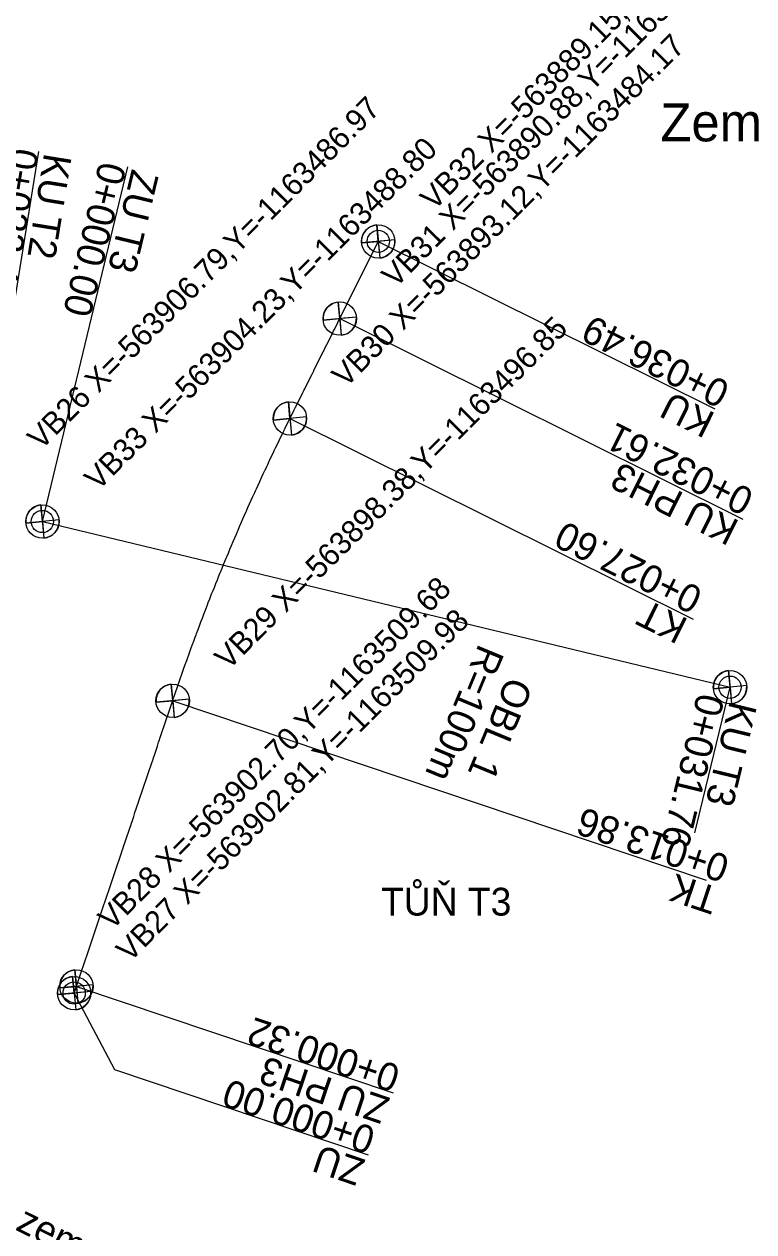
# Model space of a CAD drawing. Extents: x -564052 to -563798, y -1163587 to -1163361.
# Drawn here: x -563905 to -563872.3, y -1163520.7 to -1163466.5 of the extents above; entities that cross this region are included whole.
import ezdxf

# ---------------------------------------------------------------- set-up
doc = ezdxf.new("R2010")
doc.units = 0
for name, color, linetype in [('4', 7, 'Continuous'), ('5', 7, 'Continuous'), ('_popis staničení PH3', 7, 'Continuous'), ('_popis staničení T2', 7, 'Continuous'), ('_popis staničení T3', 7, 'Continuous'), ('_rám C35', 7, 'Continuous'), ('Default', 7, 'Continuous')]:
    doc.layers.add(name, color=color, linetype=linetype)

msp = doc.modelspace()

# ---------------------------------------------------------------- linework, layer by layer
msp.add_lwpolyline([(-563902.805, -1163509.983), (-563902.486, -1163509.036), (-563902.357, -1163508.652), (-563902.167, -1163508.088), (-563901.848, -1163507.14), (-563901.528, -1163506.193), (-563901.209, -1163505.245), (-563900.89, -1163504.297), (-563900.761, -1163503.913), (-563900.665, -1163503.629), (-563900.664, -1163503.625), (-563900.605, -1163503.45), (-563900.571, -1163503.349), (-563900.546, -1163503.275), (-563900.487, -1163503.099), (-563900.428, -1163502.924), (-563900.369, -1163502.749), (-563900.31, -1163502.573), (-563900.252, -1163502.402), (-563900.251, -1163502.398), (-563900.191, -1163502.223), (-563900.132, -1163502.047), (-563900.073, -1163501.872), (-563900.014, -1163501.697), (-563899.955, -1163501.521), (-563899.933, -1163501.454), (-563899.896, -1163501.346), (-563899.837, -1163501.171), (-563899.778, -1163500.995), (-563899.719, -1163500.82), (-563899.66, -1163500.645), (-563899.613, -1163500.506), (-563899.601, -1163500.469), (-563899.542, -1163500.294), (-563899.483, -1163500.119), (-563899.424, -1163499.943), (-563899.365, -1163499.768), (-563899.306, -1163499.593), (-563899.294, -1163499.559), (-563899.247, -1163499.417), (-563899.188, -1163499.242), (-563899.129, -1163499.067), (-563899.07, -1163498.891), (-563899.011, -1163498.716), (-563898.975, -1163498.611), (-563898.952, -1163498.541), (-563898.893, -1163498.366), (-563898.833, -1163498.19), (-563898.774, -1163498.015), (-563898.715, -1163497.84), (-563898.656, -1163497.664), (-563898.656, -1163497.663), (-563898.597, -1163497.489), (-563898.538, -1163497.314), (-563898.479, -1163497.138), (-563898.42, -1163496.963), (-563898.381, -1163496.847), (-563898.361, -1163496.788), (-563898.337, -1163496.716), (-563898.302, -1163496.612), (-563898.242, -1163496.437), (-563898.182, -1163496.262), (-563898.122, -1163496.087), (-563898.061, -1163495.913), (-563898.012, -1163495.77), (-563898, -1163495.738), (-563897.939, -1163495.563), (-563897.878, -1163495.389), (-563897.816, -1163495.215), (-563897.753, -1163495.04), (-563897.691, -1163494.866), (-563897.677, -1163494.828), (-563897.628, -1163494.692), (-563897.625, -1163494.685), (-563897.565, -1163494.518), (-563897.501, -1163494.345), (-563897.437, -1163494.171), (-563897.373, -1163493.997), (-563897.333, -1163493.889), (-563897.309, -1163493.824), (-563897.244, -1163493.651), (-563897.179, -1163493.478), (-563897.113, -1163493.305), (-563897.048, -1163493.132), (-563896.982, -1163492.959), (-563896.979, -1163492.953), (-563896.915, -1163492.786), (-563896.849, -1163492.614), (-563896.82, -1163492.541), (-563896.781, -1163492.441), (-563896.714, -1163492.269), (-563896.646, -1163492.097), (-563896.617, -1163492.021), (-563896.578, -1163491.925), (-563896.51, -1163491.753), (-563896.442, -1163491.581), (-563896.373, -1163491.409), (-563896.303, -1163491.238), (-563896.245, -1163491.093), (-563896.234, -1163491.066), (-563896.164, -1163490.895), (-563896.094, -1163490.724), (-563896.023, -1163490.553), (-563895.967, -1163490.416), (-563895.952, -1163490.382), (-563895.881, -1163490.211), (-563895.863, -1163490.169), (-563895.81, -1163490.04), (-563895.738, -1163489.87), (-563895.666, -1163489.7), (-563895.593, -1163489.529), (-563895.521, -1163489.359), (-563895.473, -1163489.248), (-563895.447, -1163489.189), (-563895.374, -1163489.019), (-563895.3, -1163488.85), (-563895.226, -1163488.68), (-563895.152, -1163488.511), (-563895.078, -1163488.342), (-563895.073, -1163488.331), (-563895.064, -1163488.311), (-563895.003, -1163488.172), (-563894.927, -1163488.003), (-563894.852, -1163487.835), (-563894.776, -1163487.666), (-563894.7, -1163487.497), (-563894.664, -1163487.419), (-563894.623, -1163487.329), (-563894.546, -1163487.16), (-563894.469, -1163486.992), (-563894.392, -1163486.824), (-563894.314, -1163486.656), (-563894.246, -1163486.51), (-563894.236, -1163486.489), (-563894.158, -1163486.321), (-563894.114, -1163486.228), (-563894.079, -1163486.154), (-563894, -1163485.986), (-563893.921, -1163485.819), (-563893.841, -1163485.652), (-563893.819, -1163485.606), (-563893.761, -1163485.485), (-563893.681, -1163485.319), (-563893.601, -1163485.152), (-563893.52, -1163484.986), (-563893.439, -1163484.819), (-563893.383, -1163484.706), (-563893.357, -1163484.653), (-563893.275, -1163484.487), (-563893.193, -1163484.322), (-563893.116, -1163484.167), (-563893.111, -1163484.156), (-563893.028, -1163483.99), (-563892.946, -1163483.825), (-563892.939, -1163483.81), (-563892.863, -1163483.659), (-563892.781, -1163483.494), (-563892.698, -1163483.328), (-563892.616, -1163483.162), (-563892.533, -1163482.997), (-563892.493, -1163482.915), (-563892.451, -1163482.831), (-563892.368, -1163482.666), (-563892.286, -1163482.5), (-563892.203, -1163482.335), (-563892.121, -1163482.169), (-563892.047, -1163482.02), (-563892.038, -1163482.003), (-563891.956, -1163481.838), (-563891.873, -1163481.672), (-563891.791, -1163481.507), (-563891.708, -1163481.341), (-563891.626, -1163481.175), (-563891.601, -1163481.125), (-563891.543, -1163481.01), (-563891.461, -1163480.844), (-563891.378, -1163480.679), (-563891.296, -1163480.513), (-563891.213, -1163480.347), (-563891.155, -1163480.23), (-563891.131, -1163480.182), (-563891.048, -1163480.016), (-563890.966, -1163479.851), (-563889.152, -1163476.21), (-563889.15, -1163476.207)])
at = {"layer": '5'}
msp.add_line((-563904.23, -1163488.796), (-563873.359, -1163496.24), dxfattribs=at)
at = {"layer": '_popis staničení PH3'}
for points in [[(-563889.152, -1163476.21), (-563874.048, -1163483.736)], [(-563890.882, -1163479.681), (-563872.786, -1163488.697)], [(-563893.116, -1163484.167), (-563875.019, -1163493.183)], [(-563898.381, -1163496.847), (-563874.436, -1163504.911)], [(-563902.805, -1163509.983), (-563900.986, -1163513.414), (-563889.599, -1163517.249)], [(-563902.704, -1163509.683), (-563888.488, -1163514.47)]]:
    msp.add_lwpolyline(points, dxfattribs=at)
for centre in [(-563889.152, -1163476.21), (-563902.805, -1163509.983)]:
    msp.add_circle(centre, 0.5, dxfattribs=at)
at = {"layer": '_popis staničení T2'}
msp.add_lwpolyline([(-563906.789, -1163486.973), (-563904.394, -1163472.165)], dxfattribs=at)
at = {"layer": '_popis staničení T3'}
for points in [[(-563904.23, -1163488.796), (-563900.388, -1163472.866)], [(-563874.936, -1163502.781), (-563873.359, -1163496.24)]]:
    msp.add_lwpolyline(points, dxfattribs=at)
for centre in [(-563904.23, -1163488.796), (-563873.359, -1163496.24)]:
    msp.add_circle(centre, 0.5, dxfattribs=at)
at = {"layer": '_rám C35'}
for p, q in [((-563889.152, -1163476.21), (-563889.222, -1163475.463)), ((-563889.152, -1163476.21), (-563889.222, -1163475.463)), ((-563889.222, -1163475.464), (-563889.083, -1163476.957)), ((-563888.405, -1163476.141), (-563889.899, -1163476.28)), ((-563889.899, -1163476.28), (-563889.152, -1163476.21)), ((-563889.899, -1163476.28), (-563889.152, -1163476.21)), ((-563888.405, -1163476.141), (-563889.152, -1163476.21)), ((-563889.152, -1163476.21), (-563889.083, -1163476.958)), ((-563890.882, -1163479.681), (-563890.951, -1163478.934)), ((-563890.881, -1163479.681), (-563890.951, -1163478.934)), ((-563890.951, -1163478.935), (-563890.812, -1163480.428)), ((-563891.629, -1163479.751), (-563890.882, -1163479.681)), ((-563891.629, -1163479.751), (-563890.881, -1163479.681)), ((-563890.135, -1163479.612), (-563891.628, -1163479.751)), ((-563890.134, -1163479.612), (-563890.882, -1163479.681)), ((-563890.882, -1163479.681), (-563890.812, -1163480.429)), ((-563893.116, -1163484.167), (-563893.186, -1163483.419)), ((-563893.116, -1163484.167), (-563893.186, -1163483.419)), ((-563893.186, -1163483.42), (-563893.047, -1163484.913)), ((-563892.37, -1163484.097), (-563893.863, -1163484.236)), ((-563892.369, -1163484.097), (-563893.116, -1163484.167)), ((-563893.863, -1163484.236), (-563893.116, -1163484.167)), ((-563893.863, -1163484.236), (-563893.116, -1163484.167)), ((-563893.116, -1163484.167), (-563893.047, -1163484.914)), ((-563904.299, -1163488.049), (-563904.16, -1163489.542)), ((-563904.23, -1163488.796), (-563904.299, -1163488.049)), ((-563904.23, -1163488.796), (-563904.299, -1163488.049)), ((-563904.977, -1163488.865), (-563904.23, -1163488.796)), ((-563904.977, -1163488.865), (-563904.23, -1163488.796)), ((-563903.483, -1163488.726), (-563904.976, -1163488.865)), ((-563903.483, -1163488.726), (-563904.23, -1163488.796)), ((-563904.23, -1163488.796), (-563904.16, -1163489.543)), ((-563873.358, -1163496.24), (-563873.428, -1163495.492)), ((-563873.428, -1163495.493), (-563873.289, -1163496.986)), ((-563873.359, -1163496.24), (-563873.428, -1163495.493)), ((-563898.451, -1163496.1), (-563898.312, -1163497.594)), ((-563898.381, -1163496.847), (-563898.451, -1163496.1)), ((-563898.381, -1163496.847), (-563898.451, -1163496.1)), ((-563874.106, -1163496.309), (-563873.359, -1163496.24)), ((-563874.106, -1163496.309), (-563873.358, -1163496.24)), ((-563872.612, -1163496.17), (-563874.105, -1163496.309)), ((-563872.611, -1163496.17), (-563873.359, -1163496.24)), ((-563873.359, -1163496.24), (-563873.289, -1163496.987)), ((-563897.634, -1163496.778), (-563899.128, -1163496.917)), ((-563899.128, -1163496.917), (-563898.381, -1163496.847)), ((-563899.128, -1163496.917), (-563898.381, -1163496.847)), ((-563897.634, -1163496.778), (-563898.381, -1163496.847)), ((-563898.381, -1163496.847), (-563898.312, -1163497.594)), ((-563902.704, -1163509.683), (-563902.773, -1163508.935)), ((-563902.773, -1163508.936), (-563902.634, -1163510.429)), ((-563902.704, -1163509.683), (-563902.773, -1163508.936)), ((-563901.957, -1163509.613), (-563903.45, -1163509.752)), ((-563902.805, -1163509.983), (-563902.875, -1163509.236)), ((-563902.805, -1163509.983), (-563902.875, -1163509.236)), ((-563902.875, -1163509.237), (-563902.736, -1163510.73)), ((-563901.957, -1163509.613), (-563902.704, -1163509.683)), ((-563902.058, -1163509.914), (-563903.552, -1163510.053)), ((-563903.552, -1163510.053), (-563902.805, -1163509.983)), ((-563903.552, -1163510.053), (-563902.805, -1163509.983)), ((-563903.451, -1163509.752), (-563902.704, -1163509.683)), ((-563903.451, -1163509.752), (-563902.704, -1163509.683)), ((-563902.058, -1163509.914), (-563902.805, -1163509.983)), ((-563902.805, -1163509.983), (-563902.736, -1163510.731)), ((-563902.704, -1163509.683), (-563902.634, -1163510.43))]:
    msp.add_line(p, q, dxfattribs=at)
for centre in [(-563889.152, -1163476.21), (-563890.882, -1163479.681), (-563893.116, -1163484.167), (-563904.23, -1163488.796), (-563873.359, -1163496.24), (-563898.381, -1163496.847), (-563902.704, -1163509.683), (-563902.805, -1163509.983)]:
    msp.add_circle(centre, 0.75, dxfattribs=at)
for centre, start, end in [((-563889.152, -1163476.21), 95.3168, 185.3168), ((-563889.152, -1163476.21), 95.3168, 185.3168), ((-563889.152, -1163476.21), 275.3168, 5.3168), ((-563890.882, -1163479.681), 95.3168, 185.3168), ((-563890.881, -1163479.681), 95.3168, 185.3168), ((-563890.882, -1163479.681), 275.3168, 5.3168), ((-563893.116, -1163484.167), 95.3168, 185.3168), ((-563893.116, -1163484.167), 95.3168, 185.3168), ((-563893.116, -1163484.167), 275.3168, 5.3168), ((-563904.23, -1163488.796), 95.3168, 185.3168), ((-563904.23, -1163488.796), 95.3168, 185.3168), ((-563904.23, -1163488.796), 275.3168, 5.3168), ((-563873.358, -1163496.24), 95.3168, 185.3168), ((-563873.359, -1163496.24), 95.3168, 185.3168), ((-563898.381, -1163496.847), 95.3168, 185.3168), ((-563898.381, -1163496.847), 95.3168, 185.3168), ((-563873.359, -1163496.24), 275.3168, 5.3168), ((-563898.381, -1163496.847), 275.3168, 5.3168), ((-563902.704, -1163509.683), 95.3168, 185.3168), ((-563902.704, -1163509.683), 95.3168, 185.3168), ((-563902.805, -1163509.983), 95.3168, 185.3168), ((-563902.805, -1163509.983), 95.3168, 185.3168), ((-563902.704, -1163509.683), 275.3168, 5.3168), ((-563902.805, -1163509.983), 275.3168, 5.3168)]:
    msp.add_arc(centre, 0.75, start, end, dxfattribs=at)

# ---------------------------------------------------------------- texts
at = {"layer": '4'}
for s, height, p in [('Zemní hrázka PH3', 1.70472, (-563876.485, -1163471.716)), ('TŮŇ T3', 1.25, (-563889.026, -1163506.501))]:
    msp.add_text(s, height=height, rotation=360, dxfattribs=at).set_placement(p)
at = {"layer": '_popis staničení PH3'}
for s, rotation, p in [('0+036.49', 153.5152, (-563873.289, -1163482.619)), ('KU ', 153.5152, (-563873.958, -1163483.962)), ('0+032.61', 153.5152, (-563872.21, -1163487.45)), ('KU PH3 ', 153.5152, (-563872.879, -1163488.793)), ('0+027.60', 153.5152, (-563874.509, -1163491.871)), ('KT ', 153.5152, (-563875.178, -1163493.213)), ('R=100m ', 247.4517, (-563884.627, -1163494.245)), ('OBL 1', 247.4517, (-563883.339, -1163495.706)), ('0+013.86', 161.3882, (-563873.306, -1163503.859)), ('TK ', 161.3882, (-563873.785, -1163505.28)), ('0+000.32', 161.3882, (-563888.089, -1163513.285)), ('ZU PH3 ', 161.3882, (-563888.568, -1163514.707)), ('0+000.00', 161.3882, (-563889.201, -1163516.064)), ('ZU ', 161.3882, (-563889.679, -1163517.486))]:
    msp.add_text(s, height=1.25, rotation=rotation, dxfattribs=at).set_placement(p)
at = {"layer": '_popis staničení T2'}
for s, p in [('0+033.46', (-563905.628, -1163471.965)), ('KU T2 ', (-563904.147, -1163472.205))]:
    msp.add_text(s, height=1.25, rotation=260.811, dxfattribs=at).set_placement(p)
at = {"layer": '_popis staničení T3'}
for s, p in [('0+000.00', (-563901.665, -1163472.571)), ('ZU T3 ', (-563900.207, -1163472.922)), ('0+031.76', (-563874.814, -1163496.452)), ('KU T3 ', (-563873.356, -1163496.804))]:
    msp.add_text(s, height=1.25, rotation=256.4433, dxfattribs=at).set_placement(p)
at = {"layer": '_rám C35'}
msp.add_text('osa zemní hrázky, tůně, odpadního příkopu, odpadního průlehu', height=1.25, rotation=333.563, dxfattribs=at).set_placement((-563908.317, -1163519.191))
at = {"layer": 'Default'}
for s, p in [('VB32 X=-563889.15,Y=-1163476.21', (-563886.652, -1163474.862)), ('VB31 X=-563890.88,Y=-1163479.68', (-563888.382, -1163478.333)), ('VB30 X=-563893.12,Y=-1163484.17', (-563890.617, -1163482.818)), ('VB26 X=-563906.79,Y=-1163486.97', (-563904.29, -1163485.624)), ('VB33 X=-563904.23,Y=-1163488.80', (-563901.73, -1163487.448)), ('VB29 X=-563898.38,Y=-1163496.85', (-563895.882, -1163495.499)), ('VB28 X=-563902.70,Y=-1163509.68', (-563901.116, -1163507.194)), ('VB27 X=-563902.81,Y=-1163509.98', (-563900.305, -1163508.635))]:
    msp.add_text(s, height=1, rotation=45, dxfattribs=at).set_placement(p)

doc.saveas('drawing.dxf')
